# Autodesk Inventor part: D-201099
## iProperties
Created: 2007-10
Part Number: D-201099
Document SubType Name: Modeling
Designer: TH
Density: 7.85 g/cm^3
Mass: 61.2 g
Surface Area: 44.7201 cm^2
Volume: 7.79617 cm^3
Material: Steel
Description: PIVOT PLATE
Component Category: Lower Component
Author: TH
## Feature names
1. Extrusion1
2. Hole1
3. Hole2
